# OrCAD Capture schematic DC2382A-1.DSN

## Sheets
1 LTC2975: size B
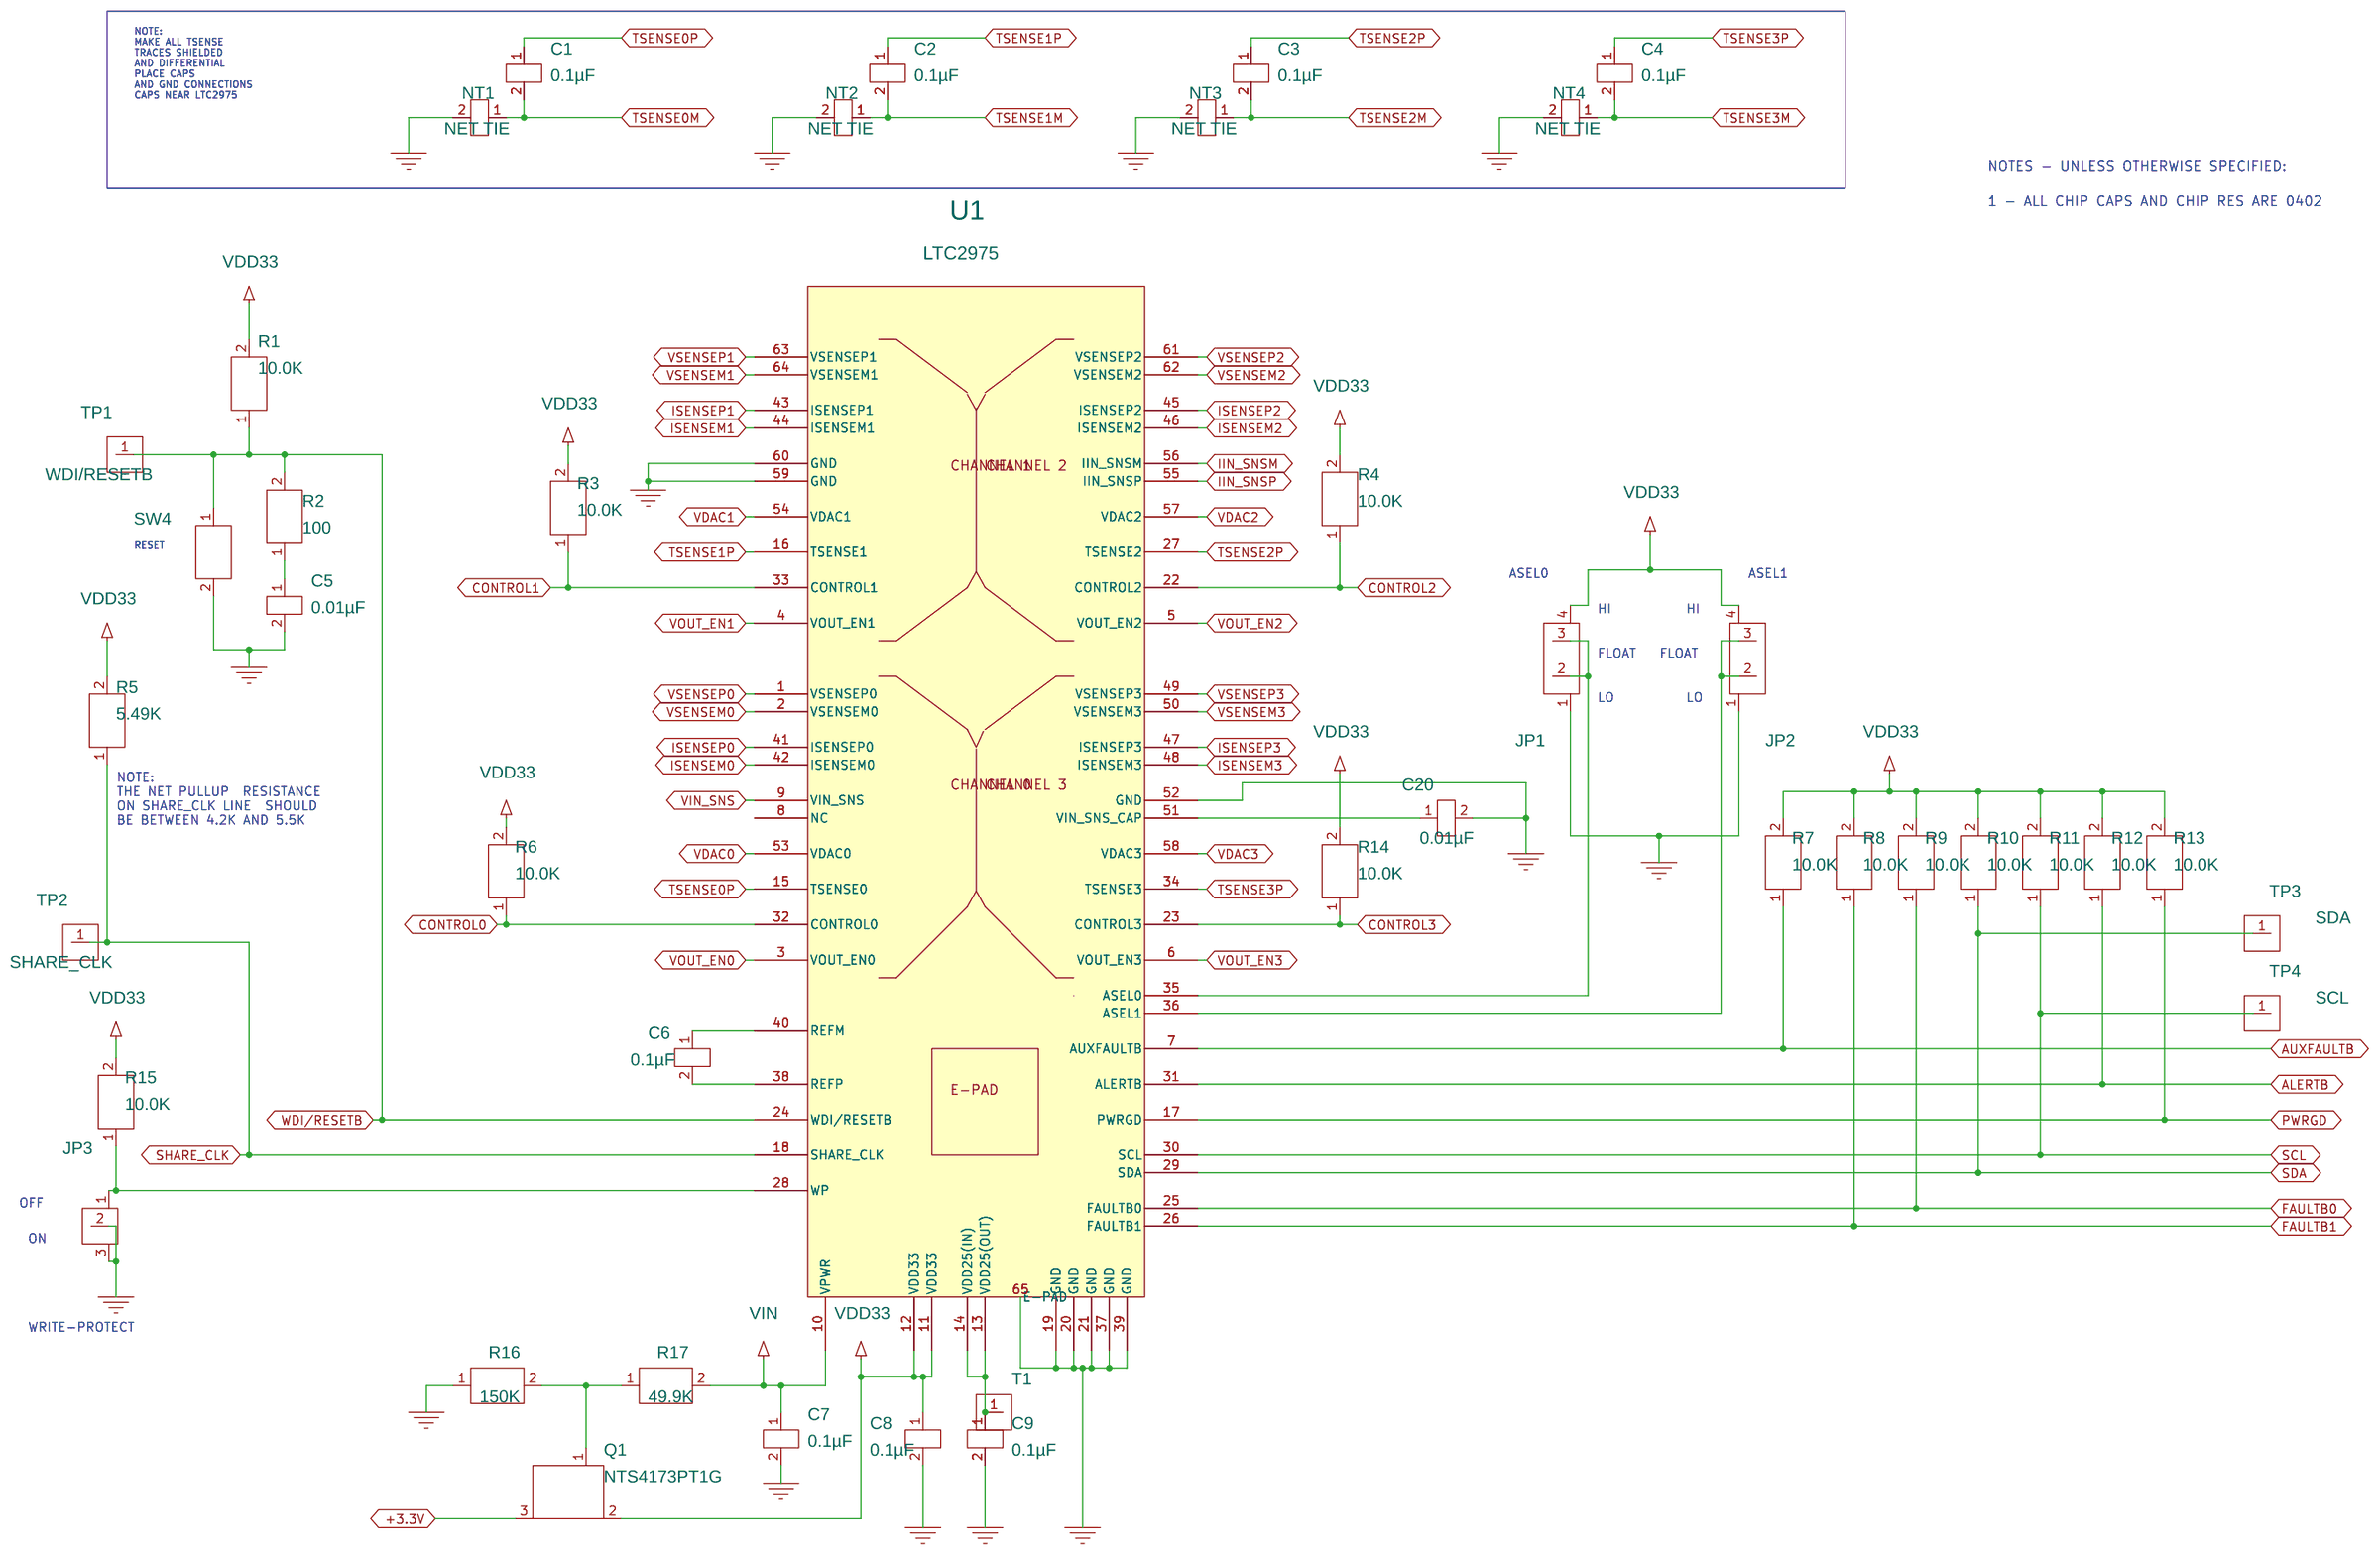
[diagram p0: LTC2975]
2 I2C & LOCAL BUS & CONTROL: size B; title: 4-CHANNEL PMBUS POWER SYSTEM MANAGER; rev: 1; company: TM
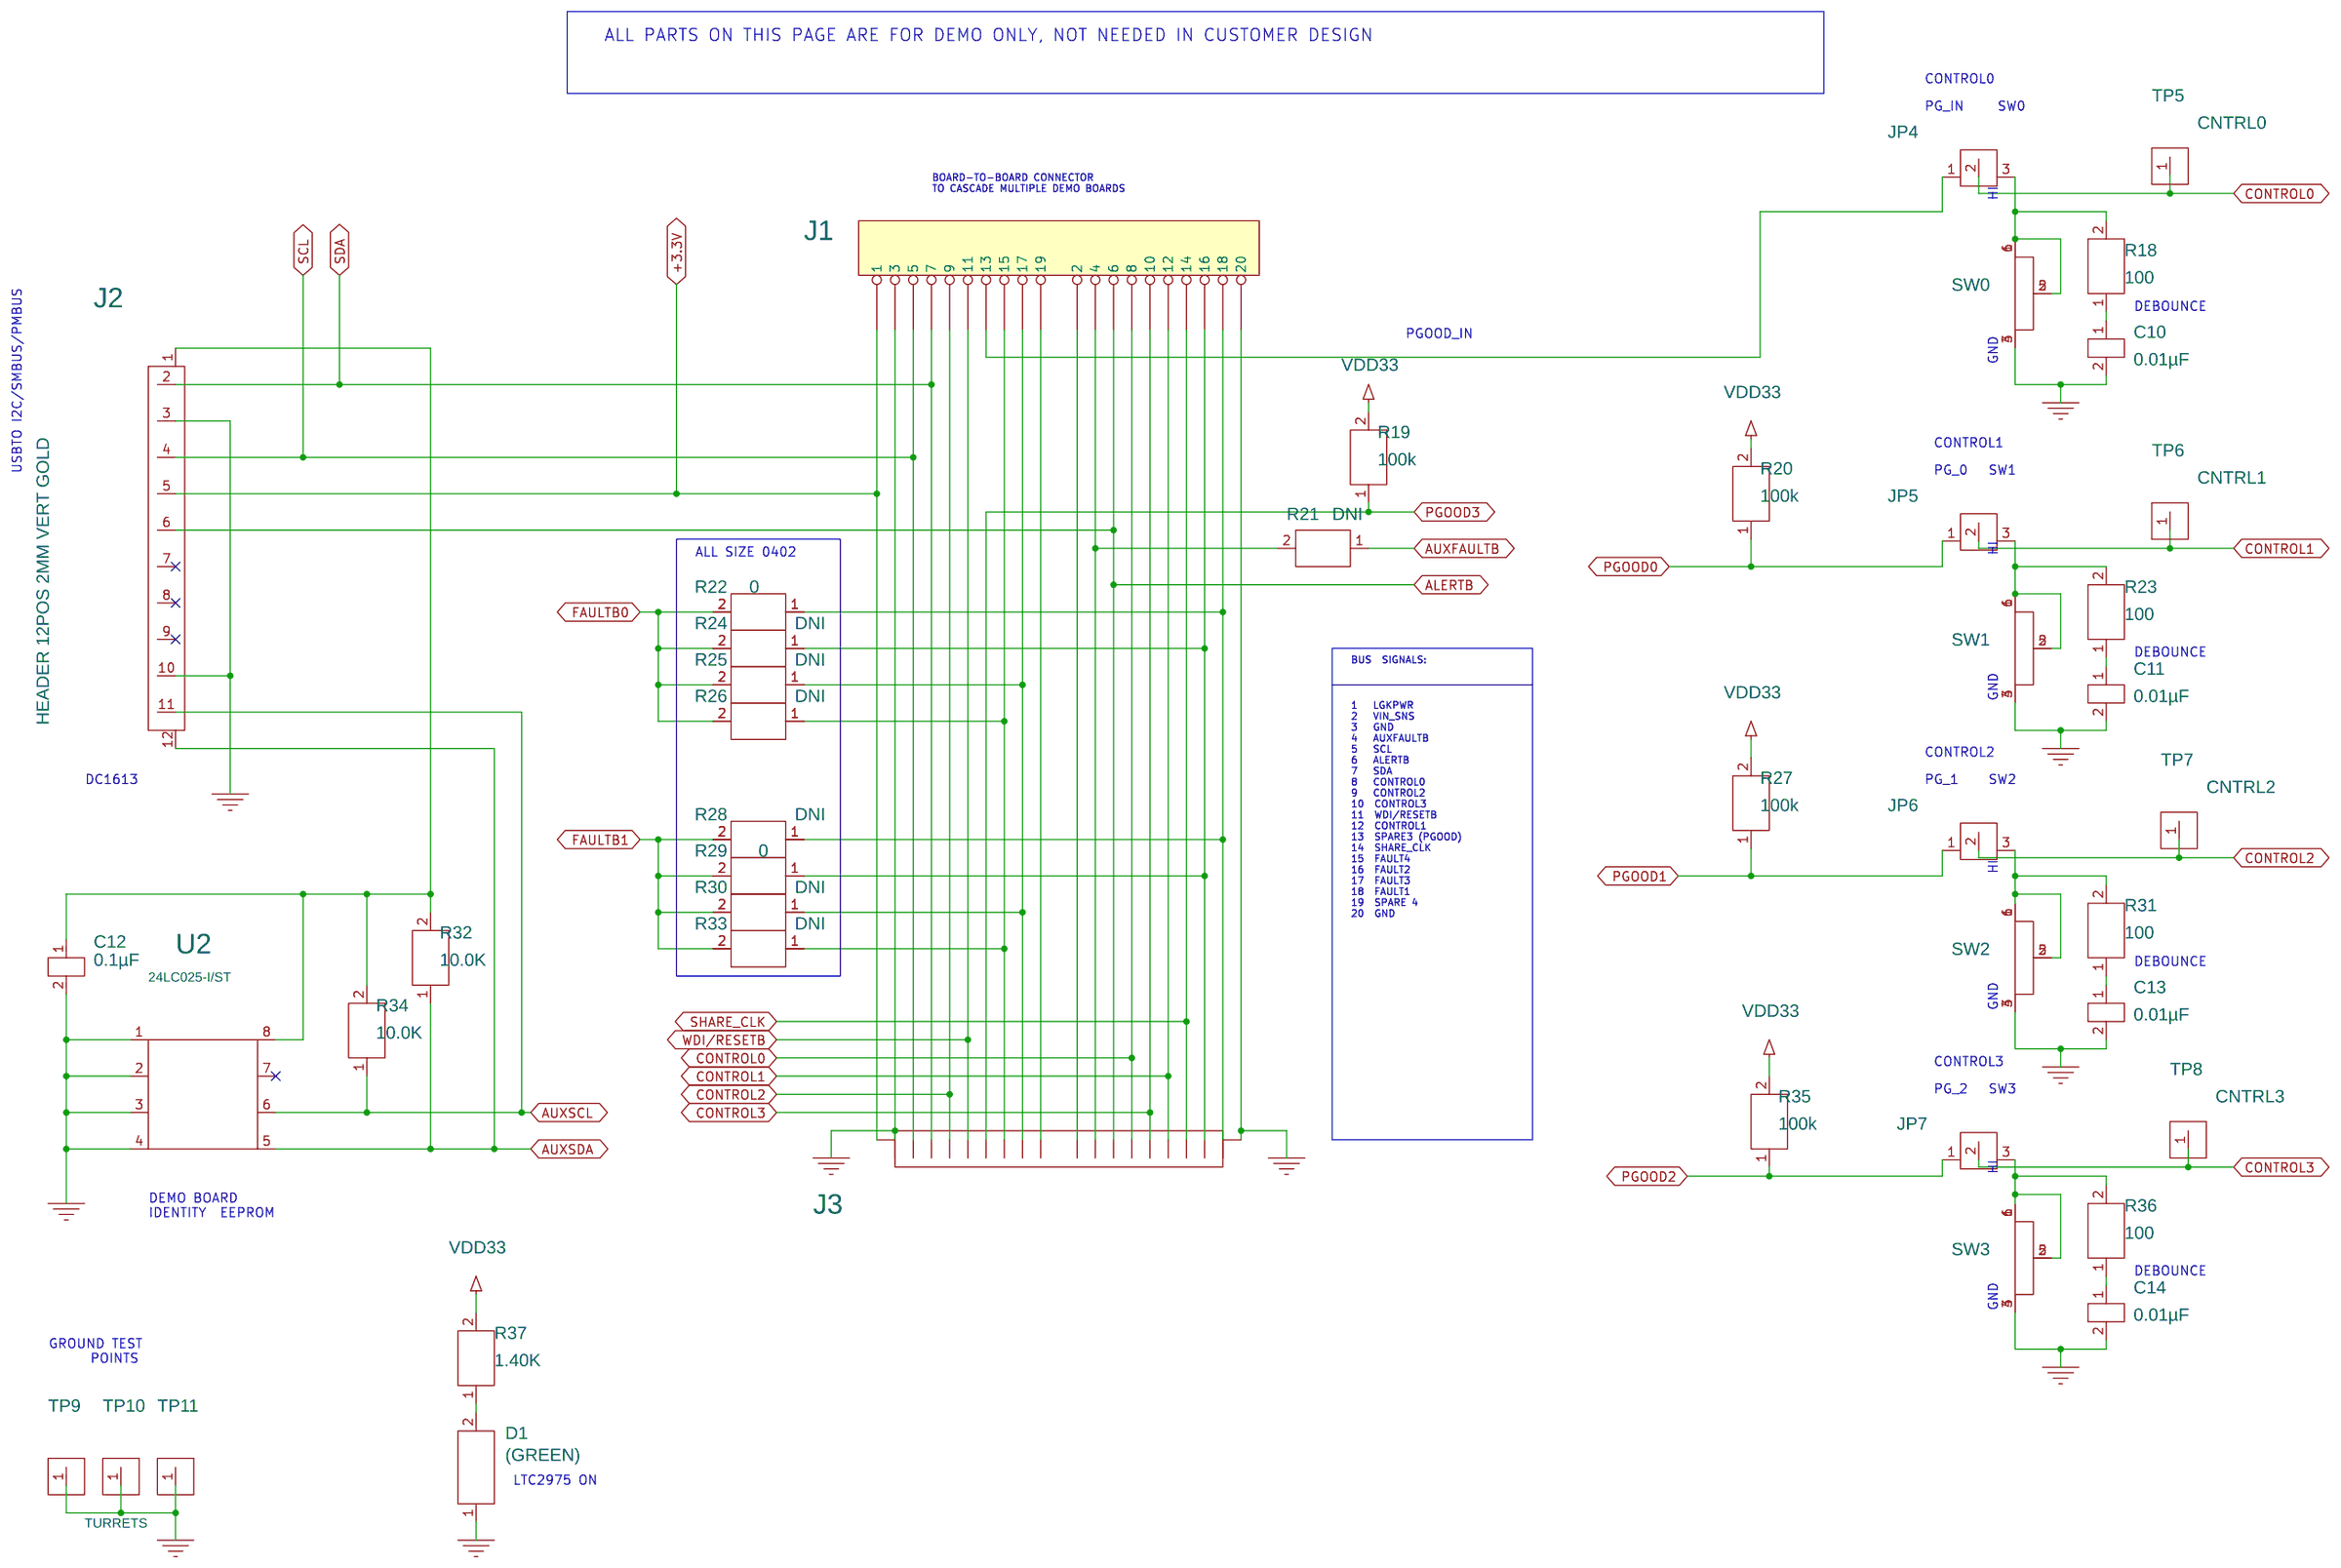
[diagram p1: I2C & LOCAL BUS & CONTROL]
3 HEADER & LDO: size B; title: 4-CHANNEL PMBUS POWER SYSTEM MANAGER; rev: 1; company: TM
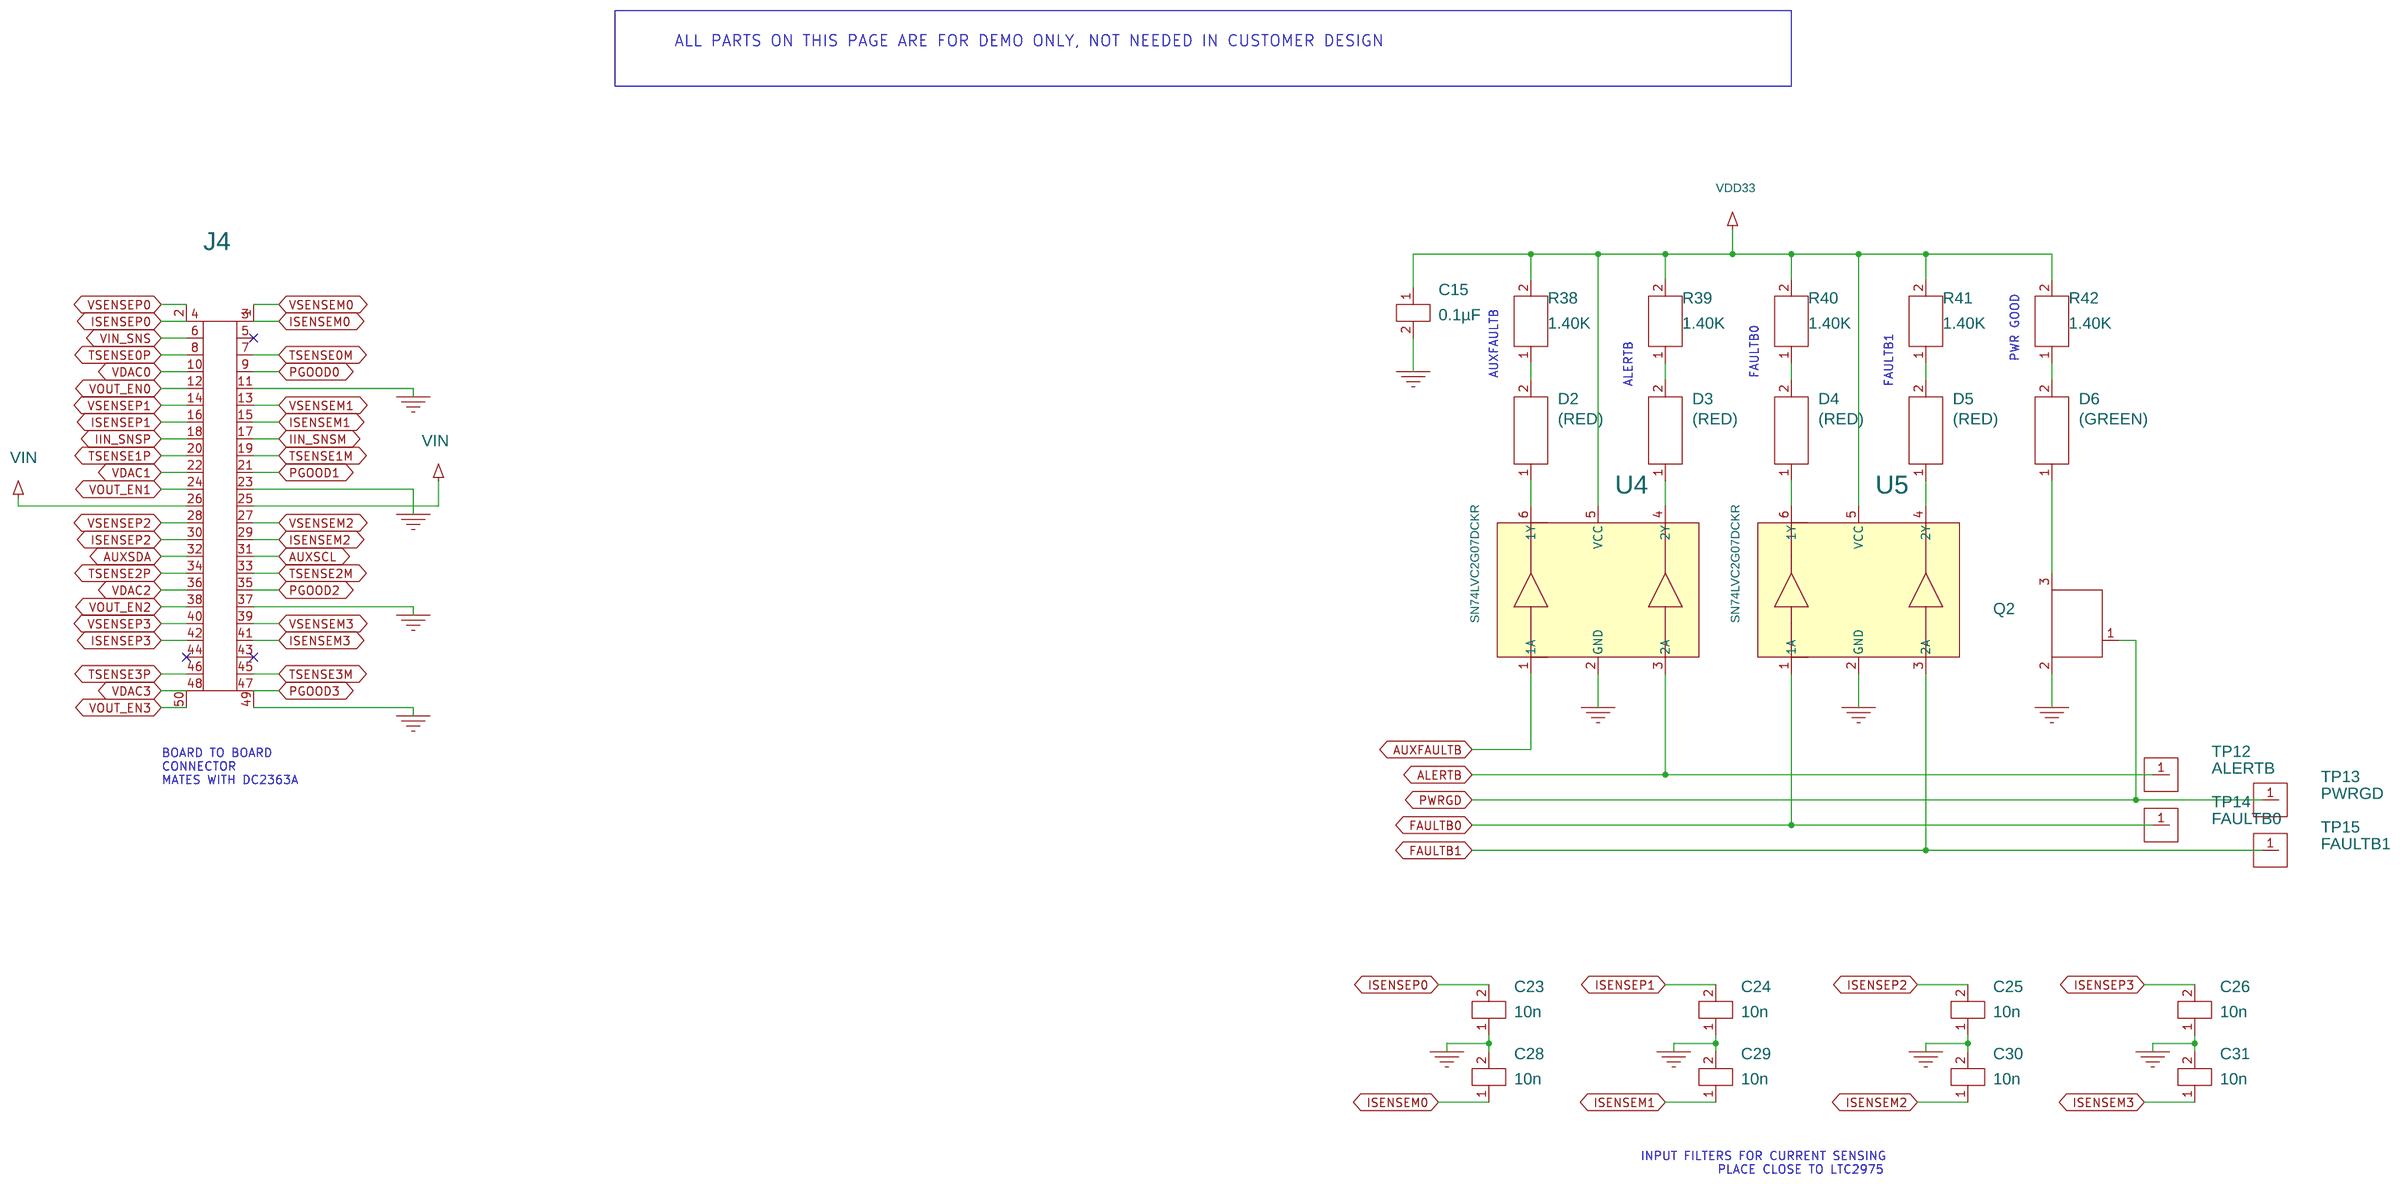
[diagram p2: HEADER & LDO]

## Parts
sheet HEADER & LDO
C15  0.1µF  [0402_(1005)]
C23  10n  [0402_(1005)]
C24  10n  [0402_(1005)]
C25  10n  [0402_(1005)]
C26  10n  [0402_(1005)]
C28  10n  [0402_(1005)]
C29  10n  [0402_(1005)]
C30  10n  [0402_(1005)]
C31  10n  [0402_(1005)]
D2  (RED)  [SML-P11MTT86]
D3  (RED)  [SML-P11MTT86]
D4  (RED)  [SML-P11MTT86]
D5  (RED)  [SML-P11MTT86]
D6  (GREEN)  [SML-P11MTT86]
J4  PPPC252LJBN-RC-DEMO  [PPPC252LJBN-RC]
Q2  2N7002  [SOT-23]
R38  1.40K  [0402_(1005)]
R39  1.40K  [0402_(1005)]
R40  1.40K  [0402_(1005)]
R41  1.40K  [0402_(1005)]
R42  1.40K  [0402_(1005)]
TP12  SMALL TURRET  [TURRETS]
TP13  SMALL TURRET  [TURRETS]
TP14  SMALL TURRET  [TURRETS]
TP15  SMALL TURRET  [TURRETS]
U4  SN74LVC2G07DCKR  [SC6-SC70V]
U5  SN74LVC2G07DCKR  [SC6-SC70V]
sheet I2C & LOCAL BUS & CONTROL
C10  0.01µF  [0402_(1005)]
C11  0.01µF  [0402_(1005)]
C12  0.1µF  [0402_(1005)]
C13  0.01µF  [0402_(1005)]
C14  0.01µF  [0402_(1005)]
D1  (GREEN)  [SML-P11MTT86]
J1  803-93-020-20-001  [803-93-020-20-001000]
J2  HEADER 12POS 2MM VERT GOLD  [HD2X6-079-MOLEX]
J3  802-40-020-20-001  [802-40-020-20-001]
JP4  JUMPER3  [TMM-103-02-L-S]
JP5  JUMPER3  [TMM-103-02-L-S]
JP6  JUMPER3  [TMM-103-02-L-S]
JP7  JUMPER3  [TMM-103-02-L-S]
R18  100  [0402_(1005)]
R19  100k  [0402_(1005)]
R20  100k  [0402_(1005)]
R21  DNI  [0402_(1005)]
R22  0  [0402_(1005)]
R23  100  [0402_(1005)]
R24  DNI  [0402_(1005)]
R25  DNI  [0402_(1005)]
R26  DNI  [0402_(1005)]
R27  100k  [0402_(1005)]
R28  DNI  [0402_(1005)]
R29  0  [0402_(1005)]
R30  DNI  [0402_(1005)]
R31  100  [0402_(1005)]
R32  10.0K  [0402_(1005)]
R33  DNI  [0402_(1005)]
R34  10.0K  [0402_(1005)]
R35  100k  [0402_(1005)]
R36  100  [0402_(1005)]
R37  1.40K  [0402_(1005)]
SW0  Slide Switch - Demo Boards  [JS202011CQN]
SW1  Slide Switch - Demo Boards  [JS202011CQN]
SW2  Slide Switch - Demo Boards  [JS202011CQN]
SW3  Slide Switch - Demo Boards  [JS202011CQN]
TP5  SMALL TURRET  [TURRETS]
TP6  SMALL TURRET  [TURRETS]
TP7  SMALL TURRET  [TURRETS]
TP8  SMALL TURRET  [TURRETS]
TP9  SMALL TURRET  [TURRETS]
TP10  SMALL TURRET  [TURRETS]
TP11  SMALL TURRET  [TURRETS]
U2  24LC025-I/ST  [8-SSOP]
sheet LTC2975
C1  0.1µF  [0402_(1005)]
C2  0.1µF  [0402_(1005)]
C3  0.1µF  [0402_(1005)]
C4  0.1µF  [0402_(1005)]
C5  0.01µF  [0402_(1005)]
C6  0.1µF  [0402_(1005)]
C7  0.1µF  [0402_(1005)]
C8  0.1µF  [0402_(1005)]
C9  0.1µF  [0402_(1005)]
C20  0.01µF  [0402_(1005)]
JP1  4 PIN 2MM JUMPER - DEMO  [TMM-104-02-L-S]
JP2  4 PIN 2MM JUMPER - DEMO  [TMM-104-02-L-S]
JP3  JUMPER3  [TMM-103-02-L-S]
NT1  NET TIE  [NETTIE]
NT2  NET TIE  [NETTIE]
NT3  NET TIE  [NETTIE]
NT4  NET TIE  [NETTIE]
Q1  NTS4173PT1G  [SC70-3]
R1  10.0K  [0402_(1005)]
R2  100  [0402_(1005)]
R3  10.0K  [0402_(1005)]
R4  10.0K  [0402_(1005)]
R5  5.49K  [0402_(1005)]
R6  10.0K  [0402_(1005)]
R7  10.0K  [0402_(1005)]
R8  10.0K  [0402_(1005)]
R9  10.0K  [0402_(1005)]
R10  10.0K  [0402_(1005)]
R11  10.0K  [0402_(1005)]
R12  10.0K  [0402_(1005)]
R13  10.0K  [0402_(1005)]
R14  10.0K  [0402_(1005)]
R15  10.0K  [0402_(1005)]
R16  150K  [0402_(1005)]
R17  49.9K  [0402_(1005)]
SW4  SW-SPDT-NO-LT TOUCH - DEMO  [EVQ-PJS04K]
T1  Via Testpoint  [VIA_TESTPOINT]
TP1  SMALL TURRET  [TURRETS]
TP2  SMALL TURRET  [TURRETS]
TP3  SMALL TURRET  [TURRETS]
TP4  SMALL TURRET  [TURRETS]
U1  LTC2975  [9X9UP]

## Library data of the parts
C1-C4 C6 C8 C9 C12 C15 = CAP_0402_0.1µF_±10%-16V-REEL: Alternate Vendor Price: $0.00
C5 C10 C11 C13 C14 C23-C26 C28-C31 = CAP_0402_0.01µF_±10%-25V-REEL: Alternate Vendor Price: $0.00
D2-D5 = LED_RED_CLEAR_(DEMO)
D1 D6 = LED_GREEN_CLEAR_(DEMO)
J4 = PPPC252LJBN-RC-DEMO(FEMALE)
Q2 = 2N7002: Alternate Vendor Price: $0.00
R37-R42 = 1.40K_±1%-0_0.063W
TP12 = SMALL_TURRET_0: Alternate Vendor Price: $0.00; Comments / Special Instructions: HARDWARE-FOR DEMO BOARD; Label1: ALERTB
TP13 = SMALL_TURRET_0: Alternate Vendor Price: $0.00; Comments / Special Instructions: HARDWARE-FOR DEMO BOARD; Label1: PWRGD
TP14 = SMALL_TURRET_0: Alternate Vendor Price: $0.00; Comments / Special Instructions: HARDWARE-FOR DEMO BOARD; Label1: FAULTB0
TP15 = SMALL_TURRET_0: Alternate Vendor Price: $0.00; Comments / Special Instructions: HARDWARE-FOR DEMO BOARD; Label1: FAULTB1
U4 U5 = SN74LVC2G07DCKR_65: Alternate Vendor Price: $0.00
J1 = RT_ANGLE_FEMALE_HEADER_-_DEMO: CONN SOCKET 20 DUAL ROW; Alternate Vendor: www.mill-max.com; Manufacturer: Mill Max
J2 = DC1613_1: Alternate Vendor Price: $0.00
J3 = RT_ANGLE_MALE_HEADER_-_DEMO: CONN PIN HEADER 20 DUAL ROW; Alternate Vendor: www.mill-max.com; Manufacturer: Mill Max; Manufacturer Part Number: 802-40-020-20-001000
JP4 = 3_PIN_2MM_JUMPER_-_DEMO_2: Comments / Special Instructions: HARDWARE-FOR DEMO BOARD
JP5 = 3_PIN_2MM_JUMPER_-_DEMO_1: Comments / Special Instructions: HARDWARE-FOR DEMO BOARD
JP6 = 3_PIN_2MM_JUMPER_-_DEMO_3: Comments / Special Instructions: HARDWARE-FOR DEMO BOARD
JP7 = 3_PIN_2MM_JUMPER_-_DEMO_4: Comments / Special Instructions: HARDWARE-FOR DEMO BOARD
R2 R18 R23 R31 R36 = RES_0402_0.063W,_1_16W
R19 = RES_0402_5.063W,_1_16W
R20 = RES_0402_6.063W,_1_16W: Alternate Vendor Price: $0.00
R21 = RES_0402_DNI_1: Alternate Vendor Price: $0.00
R22 R29 = RES_0402_0.063W,_1_16W-REEL: Alternate Vendor Price: $0.00
R24-R26 R28 R30 R33 = RES_0402_DNI_1
R27 R35 = RES_0402_6.063W,_1_16W
R32 R34 = 10.0K_±1%-0_0.1W_-_REEL
SW0-SW3 = Slide_Switch_-_DEMO_2: Alternate Vendor Price: $0.00; Comments / Special Instructions: HARDWARE-FOR DEMO BOARD; Price Each: $0.44
TP5 = SMALL_TURRET_0: Alternate Vendor Price: $0.00; Comments / Special Instructions: HARDWARE-FOR DEMO BOARD; Label1: CNTRL0
TP6 = SMALL_TURRET_0: Alternate Vendor Price: $0.00; Comments / Special Instructions: HARDWARE-FOR DEMO BOARD; Label1: CNTRL1
TP7 = SMALL_TURRET_0: Alternate Vendor Price: $0.00; Comments / Special Instructions: HARDWARE-FOR DEMO BOARD; Label1: CNTRL2
TP8 = SMALL_TURRET_0: Alternate Vendor Price: $0.00; Comments / Special Instructions: HARDWARE-FOR DEMO BOARD; Label1: CNTRL3
TP9-TP11 = SMALL_TURRET_0: Alternate Vendor Price: $0.00; Comments / Special Instructions: HARDWARE-FOR DEMO BOARD; Label1: GND
U2 = 24LC025-I_ST_-_TSSOP
C7 = CAP_0402_0.1µF_±10%-25V-REEL: Alternate Vendor Price: $0.00
C20 = 0_0.01µF_±10%-25V-REEL
JP1 JP2 = 4_PIN_2MM_JUMPER_-_DEMO_2: Comments / Special Instructions: HARDWARE-FOR DEMO BOARD
JP3 = 3_PIN_2MM_JUMPER_-_DEMO_0: Comments / Special Instructions: HARDWARE-FOR DEMO BOARD
NT1-NT4 = NET_TIE_0
Q1 = NTS4173PT1G_SOT-23
R1 R3 R6-R13 R15 = RES_0402_0.1W,_1_10W
R4 R14 = RES_0402_0.1W,_1_10W: Alternate Vendor Price: $0.00
R5 = RES_0402_0.063W,_1_16
R16 = RES_0402_2.063W,_1_16W
R17 = RES_0402_1.063W,_1_16
SW4 = SW-SPDT-NO-LT_TOUCH_-_DEMO_0
T1 = Via_Testpoint_1: Alternate Vendor Price: $0.00; Comments / Special Instructions: HARDWARE-FOR DEMO BOARD
TP1 = SMALL_TURRET_0: Alternate Vendor Price: $0.00; Comments / Special Instructions: HARDWARE-FOR DEMO BOARD; Label1: WDI/RESETB
TP2 = SMALL_TURRET_0: Alternate Vendor Price: $0.00; Comments / Special Instructions: HARDWARE-FOR DEMO BOARD; Label1: SHARE_CLK
TP3 = SMALL_TURRET_0: Alternate Vendor Price: $0.00; Comments / Special Instructions: HARDWARE-FOR DEMO BOARD; Label1: SDA
TP4 = SMALL_TURRET_0: Alternate Vendor Price: $0.00; Comments / Special Instructions: HARDWARE-FOR DEMO BOARD; Label1: SCL
U1 = LTC2974_9x9_QFN_UP64_21: LTC2974 Package Part; Alternate Vendor: N/A; Alternate Vendor Part Number: N/A; Alternate Vendor Price: $0.00; Datasheet Location: \\Mcnally2\Datasheets\N/A; Demo Board Manufacturer: Linear Technology; Demo Board Part Number: LTC2974; Demo Board Quantity Available In Stock: N/A; Digikey Link: N/A; Digikey Part Number: N/A; Electrical Symbol Approved: Yes; Electrical Symbol Check Against Datasheet: Sean McNally; Electrical Symbol Drawn: Sean McNally; Electrical Symbol Drawn Date: Wednesday, December 08, 2010; Electrical Symbol Rev Code: 0; Electrical Symbol Revision: 0; Engineer's Qty: N/A; Garrett Part Number: N/A; Label1: N/A; Label2: N/A; Label3: N/A; Last Update: Wednesday, December 08, 2010; Manufacturer: Linear Technology; Manufacturer Part Number: LTC2974; Order Status: N/A; Other Names: N/A; Packaging: N/A; Price Each: $0.00; Qty In House: N/A; Quantity Available: N/A; RoHS Replacement: N/A; RoHS Status: Lead free / RoHS Compliant; Standard Package: N/A; Tolerance: N/A; Volts/Amps: N/A; Volts/Watts: N/A

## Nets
+3.3V: J1.1 J2.5 J3.1 Q1.3
GND: C5.2 C7.2 C8.2 C9.2 C10.2 C11.2 C12.2 C13.2 C14.2 C15.2 C20.2 C23.1 C24.1 C25.1 C26.1 C28.2 C29.2 C30.2 C31.2 D1.1 J1.3 J1.20 J2.3 J2.10 J3.2 J3.20 J4.11 J4.23 J4.37 J4.49 JP1.1 JP2.1 JP3.2 JP3.3 NT1.2 NT2.2 NT3.2 NT4.2 Q2.2 R16.1 SW0.3 SW0.4 SW1.3 SW1.4 SW2.3 SW2.4 SW3.3 SW3.4 SW4.2 TP9.1 TP10.1 TP11.1 U1.19(GND) U1.20(GND) U1.21(GND) U1.37(GND) U1.39(GND) U1.52(GND) U1.59(GND) U1.60(GND) U1.65(E-PAD) U2.1 U2.2 U2.3 U2.4 U4.2(GND) U5.2(GND)
VDD33: C8.1 C15.1 JP1.4 JP2.4 Q1.2 R1.2 R3.2 R4.2 R5.2 R6.2 R7.2 R8.2 R9.2 R10.2 R11.2 R12.2 R13.2 R14.2 R15.2 R19.2 R20.2 R27.2 R35.2 R37.2 R38.2 R39.2 R40.2 R41.2 R42.2 U1.11(VDD33) U1.12(VDD33) U4.5(VCC) U5.5(VCC)
VIN: C7.1 J4.25 J4.26 R17.2 U1.10(VPWR)
VIN_SNS: J4.6 U1.9(VIN_SNS)
ALERTB: J1.6 J2.6 J3.13 R12.1 TP12.1 U1.31(ALERTB) U4.3(2A)
AUXFAULTB: R7.1 R21.1 U1.7(AUXFAULTB) U4.1(1A)
AUXSCL: J2.11 J4.31 R34.1 U2.6
AUXSDA: J2.12 J4.32 R32.1 U2.5
CONTROL0: J1.8 J3.14 JP4.2 R6.1 TP5.1 U1.32(CONTROL0)
CONTROL1: J1.12 J3.16 JP5.2 R3.1 TP6.1 U1.33(CONTROL1)
CONTROL2: J1.9 J3.5 JP6.2 R4.1 TP7.1 U1.22(CONTROL2)
CONTROL3: J1.10 J3.15 JP7.2 R14.1 TP8.1 U1.23(CONTROL3)
FAULTB0: R9.1 R22.2 R24.2 R25.2 R26.2 TP14.1 U1.25(FAULTB0) U5.1(1A)
FAULTB1: R8.1 R28.2 R29.2 R30.2 R33.2 TP15.1 U1.26(FAULTB1) U5.3(2A)
IIN_SNSM: J4.17 U1.56(IIN_SNSM)
IIN_SNSP: J4.18 U1.55(IIN_SNSP)
ISENSEM0: C28.1 J4.3 U1.42(ISENSEM0)
ISENSEM1: C29.1 J4.15 U1.44(ISENSEM1)
ISENSEM2: C30.1 J4.29 U1.46(ISENSEM2)
ISENSEM3: C31.1 J4.41 U1.48(ISENSEM3)
ISENSEP0: C23.2 J4.4 U1.41(ISENSEP0)
ISENSEP1: C24.2 J4.16 U1.43(ISENSEP1)
ISENSEP2: C25.2 J4.30 U1.45(ISENSEP2)
ISENSEP3: C26.2 J4.42 U1.47(ISENSEP3)
PGOOD0: J4.9 JP5.1 R20.1
PGOOD1: J4.21 JP6.1 R27.1
PGOOD2: J4.35 JP7.1 R35.1
PGOOD3: J3.7 J4.47 R19.1
PWRGD: Q2.1 R13.1 TP13.1 U1.17(PWRGD)
SCL: J1.5 J2.4 J3.3 R11.1 TP4.1 U1.30(SCL)
SDA: J1.7 J2.2 J3.4 R10.1 TP3.1 U1.29(SDA)
SHARE_CLK: J1.14 J3.17 R5.1 TP2.1 U1.18(SHARE_CLK)
TSENSE0M: C1.2 J4.7 NT1.1
TSENSE0P: C1.1 J4.8 U1.15(TSENSE0)
TSENSE1M: C2.2 J4.19 NT2.1
TSENSE1P: C2.1 J4.20 U1.16(TSENSE1)
TSENSE2M: C3.2 J4.33 NT3.1
TSENSE2P: C3.1 J4.34 U1.27(TSENSE2)
TSENSE3M: C4.2 J4.45 NT4.1
TSENSE3P: C4.1 J4.46 U1.34(TSENSE3)
VDAC0: J4.10 U1.53(VDAC0)
VDAC1: J4.22 U1.54(VDAC1)
VDAC2: J4.36 U1.57(VDAC2)
VDAC3: J4.48 U1.58(VDAC3)
VOUT_EN0: J4.12 U1.3(VOUT_EN0)
VOUT_EN1: J4.24 U1.4(VOUT_EN1)
VOUT_EN2: J4.38 U1.5(VOUT_EN2)
VOUT_EN3: J4.50 U1.6(VOUT_EN3)
VSENSEM0: J4.1 U1.2(VSENSEM0)
VSENSEM1: J4.13 U1.64(VSENSEM1)
VSENSEM2: J4.27 U1.62(VSENSEM2)
VSENSEM3: J4.39 U1.50(VSENSEM3)
VSENSEP0: J4.2 U1.1(VSENSEP0)
VSENSEP1: J4.14 U1.63(VSENSEP1)
VSENSEP2: J4.28 U1.61(VSENSEP2)
VSENSEP3: J4.40 U1.49(VSENSEP3)
WDI/RESETB: J1.11 J3.6 R1.1 R2.2 SW4.1 TP1.1 U1.24(WDI/RESETB)
N3766043: JP3.1 R15.1 U1.28(WP)
N3815647: JP2.2 JP2.3 U1.36(ASEL1)
N3849131: C5.1 R2.1
N16693160: J1.15 J3.8 R26.1 R33.1
N16693176: J1.16 J3.18 R24.1 R29.1
N16693182: J1.17 J3.9 R25.1 R30.1
N16693406: J1.19 J3.10
N16693444: J1.18 J3.19 R22.1 R28.1
N16693870: J1.4 J3.12 R21.2
N16693882: J1.2 J3.11
N16694346: C12.1 J2.1 R32.2 R34.2 U2.8
N16752847: C11.1 R23.1
N16752995: JP5.3 R23.2 SW1.1 SW1.2 SW1.5 SW1.6
N16753485: JP6.3 R31.2 SW2.1 SW2.2 SW2.5 SW2.6
N16754147: JP7.3 R36.2 SW3.1 SW3.2 SW3.5 SW3.6
N16754155: C14.1 R36.1
N16797396: JP1.2 JP1.3 U1.35(ASEL0)
N17248382: C20.1 U1.51(VIN_SNS_CAP)
N17388553: C9.1 T1.1 U1.13(VDD25(OUT)) U1.14(VDD25(IN))
N17677123: JP4.3 R18.2 SW0.1 SW0.2 SW0.5 SW0.6
N17677144: C10.1 R18.1
N17686023: J1.13 JP4.1
N22404363: D6.1 Q2.3
N22404379: D6.2 R42.1
N22404544: D2.2 R38.1
N22404558: D5.2 R41.1
N22404560: D4.2 R40.1
N22404797: D5.1 U5.4(2Y)
N22404799: D4.1 U5.6(1Y)
N22404821: D3.2 R39.1
N22438237: D2.1 U4.6(1Y)
N22438239: D3.1 U4.4(2Y)
N22586840: Q1.1 R16.2 R17.1
N22804559: C6.1 U1.40(REFM)
N22804947: C6.2 U1.38(REFP)
N23329690: D1.2 R37.1
N23826256: C13.1 R31.1

Not connected (* = marked no-connect by the designer): J2 7* 8* 9*; J4 5* 43* 44*; U1 8(NC); U2 7*

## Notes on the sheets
sheet 1
- NOTE:
  MAKE ALL TSENSE
  TRACES SHIELDED
  AND DIFFERENTIAL
  PLACE CAPS
  AND GND CONNECTIONS
  CAPS NEAR LTC2975
- NOTES - UNLESS OTHERWISE SPECIFIED:
- 1 - ALL CHIP CAPS AND CHIP RES ARE 0402
- RESET
- ASEL0
- ASEL1
- HI
- HI
- FLOAT
- FLOAT
- LO
- LO
- NOTE:
  THE NET PULLUP  RESISTANCE
  ON SHARE_CLK LINE  SHOULD
  BE BETWEEN 4.2K AND 5.5K
- OFF
- ON
- WRITE-PROTECT
sheet 2
- ALL PARTS ON THIS PAGE ARE FOR DEMO ONLY, NOT NEEDED IN CUSTOMER DESIGN
- CONTROL0
- PG_IN
- SW0
- BOARD-TO-BOARD CONNECTOR
  TO CASCADE MULTIPLE DEMO BOARDS
- HI
- DEBOUNCE
- PGOOD_IN
- GND
- CONTROL1
- PG_0
- SW1
- USBTO I2C/SMBUS/PMBUS
- ALL SIZE 0402
- HI
- BUS  SIGNALS:
- DEBOUNCE
- 1   LGKPWR
  2   VIN_SNS
  3   GND
  4   AUXFAULTB
  5   SCL
  6   ALERTB
  7   SDA
  8   CONTROL0
  9   CONTROL2
  10  CONTROL3
  11  WDI/RESETB
  12  CONTROL1
  13  SPARE3 (PGOOD)
  14  SHARE_CLK
  15  FAULT4
  16  FAULT2
  17  FAULT3
  18  FAULT1
  19  SPARE 4
  20  GND
- GND
- CONTROL2
- DC1613
- PG_1
- SW2
- HI
- DEBOUNCE
- GND
- CONTROL3
- PG_2
- SW3
- HI
- DEMO BOARD
  IDENTITY  EEPROM
- DEBOUNCE
- GND
- GROUND TEST
        POINTS
- LTC2975 ON
sheet 3
- ALL PARTS ON THIS PAGE ARE FOR DEMO ONLY, NOT NEEDED IN CUSTOMER DESIGN
- PWR GOOD
- AUXFAULTB
- ALERTB
- FAULTB0
- FAULTB1
- BOARD TO BOARD
  CONNECTOR
  MATES WITH DC2363A
- INPUT FILTERS FOR CURRENT SENSING
              PLACE CLOSE TO LTC2975
